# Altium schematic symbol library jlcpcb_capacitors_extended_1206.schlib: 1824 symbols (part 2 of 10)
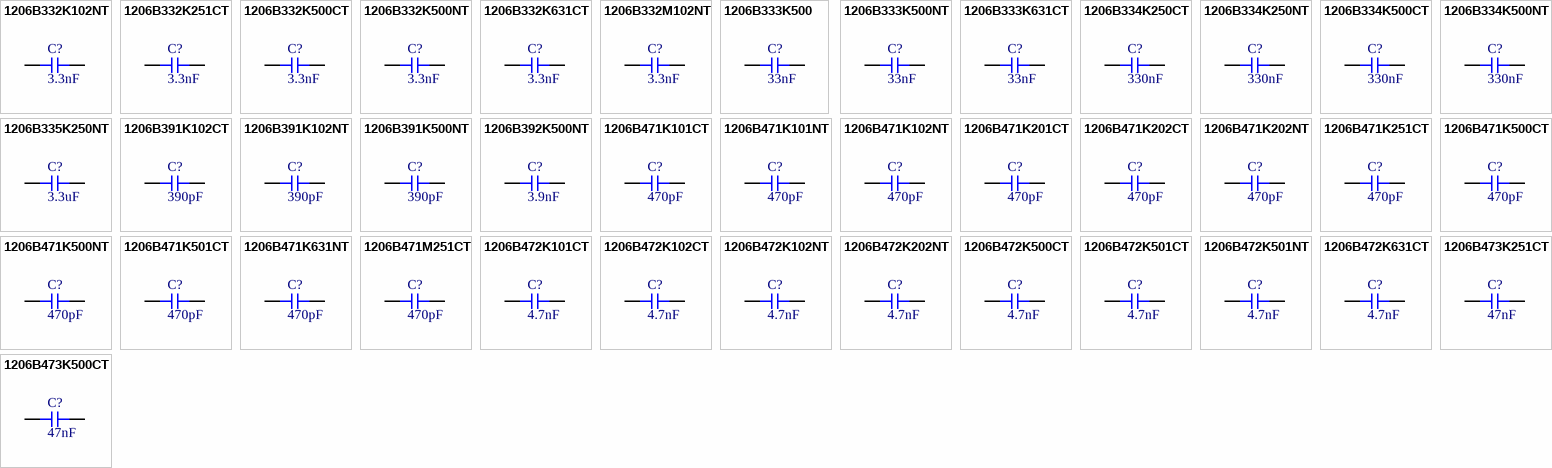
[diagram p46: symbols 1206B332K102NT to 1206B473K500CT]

## 1206B471K102NT
designator C?  Capacitance: 470pF  (hidden comment: *)
Capacitor, Ceramic (MLCC), 470pF, ±10%, 1kV, X7R, ±10%, SMD 1206; Manufacturer: FH(Guangdong Fenghua Advanced Tech); Manufacturer Part Number: 1206B471K102NT
footprint CAP-1206 (1206 (3216M) Capacitor)
pins: 1, 2

## 1206B471K201CT
designator C?  Capacitance: 470pF  (hidden comment: *)
Capacitor, Ceramic (MLCC), 470pF, ±10%, 200V, X7R, ±10%, SMD 1206; Manufacturer: Walsin Tech Corp; Manufacturer Part Number: 1206B471K201CT
footprint CAP-1206 (1206 (3216M) Capacitor)
pins: 1, 2

## 1206B471K202CT
designator C?  Capacitance: 470pF  (hidden comment: *)
Capacitor, Ceramic (MLCC), 470pF, ±10%, 2kV, X7R, ±10%, SMD 1206; Manufacturer: Walsin Tech Corp; Manufacturer Part Number: 1206B471K202CT
footprint CAP-1206 (1206 (3216M) Capacitor)
pins: 1, 2

## 1206B471K202NT
designator C?  Capacitance: 470pF  (hidden comment: *)
Capacitor, Ceramic (MLCC), 470pF, ±10%, 2kV, X7R, ±10%, SMD 1206; Manufacturer: FH(Guangdong Fenghua Advanced Tech); Manufacturer Part Number: 1206B471K202NT
footprint CAP-1206 (1206 (3216M) Capacitor)
pins: 1, 2

## 1206B471K251CT
designator C?  Capacitance: 470pF  (hidden comment: *)
Capacitor, Ceramic (MLCC), 470pF, ±10%, 250V, X7R, ±10%, SMD 1206; Manufacturer: Walsin Tech Corp; Manufacturer Part Number: 1206B471K251CT
footprint CAP-1206 (1206 (3216M) Capacitor)
pins: 1, 2

## 1206B471K500CT
designator C?  Capacitance: 470pF  (hidden comment: *)
Capacitor, Ceramic (MLCC), 470pF, ±10%, 50V, X7R, ±10%, SMD 1206; Manufacturer: Walsin Tech Corp; Manufacturer Part Number: 1206B471K500CT
footprint CAP-1206 (1206 (3216M) Capacitor)
pins: 1, 2

## 1206B471K500NT
designator C?  Capacitance: 470pF  (hidden comment: *)
Capacitor, Ceramic (MLCC), 470pF, ±10%, 50V, X7R, ±10%, SMD 1206; Manufacturer: FH(Guangdong Fenghua Advanced Tech); Manufacturer Part Number: 1206B471K500NT
footprint CAP-1206 (1206 (3216M) Capacitor)
pins: 1, 2

## 1206B471K501CT
designator C?  Capacitance: 470pF  (hidden comment: *)
Capacitor, Ceramic (MLCC), 470pF, ±10%, 500V, X7R, ±10%, SMD 1206; Manufacturer: Walsin Tech Corp; Manufacturer Part Number: 1206B471K501CT
footprint CAP-1206 (1206 (3216M) Capacitor)
pins: 1, 2

## 1206B471K631NT
designator C?  Capacitance: 470pF  (hidden comment: *)
Capacitor, Ceramic (MLCC), 470pF, ±10%, 630V, ±10%, SMD 1206; Manufacturer: FH(Guangdong Fenghua Advanced Tech); Manufacturer Part Number: 1206B471K631NT
footprint CAP-1206 (1206 (3216M) Capacitor)
pins: 1, 2

## 1206B471M251CT
designator C?  Capacitance: 470pF  (hidden comment: *)
Capacitor, Ceramic (MLCC), 470pF, ±20%, 250V, X7R, ±20%, SMD 1206; Manufacturer: Walsin Tech Corp; Manufacturer Part Number: 1206B471M251CT
footprint CAP-1206 (1206 (3216M) Capacitor)
pins: 1, 2

## 1206B472K101CT
designator C?  Capacitance: 4.7nF  (hidden comment: *)
Capacitor, Ceramic (MLCC), 4.7nF, ±10%, 100V, X7R, ±10%, SMD 1206; Manufacturer: Walsin Tech Corp; Manufacturer Part Number: 1206B472K101CT
footprint CAP-1206 (1206 (3216M) Capacitor)
pins: 1, 2

## 1206B472K102CT
designator C?  Capacitance: 4.7nF  (hidden comment: *)
Capacitor, Ceramic (MLCC), 4.7nF, ±10%, 1kV, X7R, ±10%, SMD 1206; Manufacturer: Walsin Tech Corp; Manufacturer Part Number: 1206B472K102CT
footprint CAP-1206 (1206 (3216M) Capacitor)
pins: 1, 2

## 1206B472K102NT
designator C?  Capacitance: 4.7nF  (hidden comment: *)
Capacitor, Ceramic (MLCC), 4.7nF, ±10%, 1kV, X7R, ±10%, SMD 1206; Manufacturer: FH(Guangdong Fenghua Advanced Tech); Manufacturer Part Number: 1206B472K102NT
footprint CAP-1206 (1206 (3216M) Capacitor)
pins: 1, 2

## 1206B472K202NT
designator C?  Capacitance: 4.7nF  (hidden comment: *)
Capacitor, Ceramic (MLCC), 4.7nF, ±10%, 2kV, X7R, ±10%, SMD 1206; Manufacturer: FH(Guangdong Fenghua Advanced Tech); Manufacturer Part Number: 1206B472K202NT
footprint CAP-1206 (1206 (3216M) Capacitor)
pins: 1, 2

## 1206B472K500CT
designator C?  Capacitance: 4.7nF  (hidden comment: *)
Capacitor, Ceramic (MLCC), 4.7nF, ±10%, 50V, X7R, ±10%, SMD 1206; Manufacturer: Walsin Tech Corp; Manufacturer Part Number: 1206B472K500CT
footprint CAP-1206 (1206 (3216M) Capacitor)
pins: 1, 2

## 1206B472K501CT
designator C?  Capacitance: 4.7nF  (hidden comment: *)
Capacitor, Ceramic (MLCC), 4.7nF, ±10%, 500V, X7R, ±10%, SMD 1206; Manufacturer: Walsin Tech Corp; Manufacturer Part Number: 1206B472K501CT
footprint CAP-1206 (1206 (3216M) Capacitor)
pins: 1, 2

## 1206B472K501NT
designator C?  Capacitance: 4.7nF  (hidden comment: *)
Capacitor, Ceramic (MLCC), 4.7nF, ±10%, 500V, X7R, ±10%, SMD 1206; Manufacturer: FH(Guangdong Fenghua Advanced Tech); Manufacturer Part Number: 1206B472K501NT
footprint CAP-1206 (1206 (3216M) Capacitor)
pins: 1, 2

## 1206B472K631CT
designator C?  Capacitance: 4.7nF  (hidden comment: *)
Capacitor, Ceramic (MLCC), 4.7nF, ±10%, 630V, X7R, ±10%, SMD 1206; Manufacturer: Walsin Tech Corp; Manufacturer Part Number: 1206B472K631CT
footprint CAP-1206 (1206 (3216M) Capacitor)
pins: 1, 2

## 1206B473K251CT
designator C?  Capacitance: 47nF  (hidden comment: *)
Capacitor, Ceramic (MLCC), 47nF, ±10%, 250V, X7R, ±10%, SMD 1206; Manufacturer: Walsin Tech Corp; Manufacturer Part Number: 1206B473K251CT
footprint CAP-1206 (1206 (3216M) Capacitor)
pins: 1, 2

## 1206B473K500CT
designator C?  Capacitance: 47nF  (hidden comment: *)
Capacitor, Ceramic (MLCC), 47nF, ±10%, 50V, X7R, ±10%, SMD 1206; Manufacturer: Walsin Tech Corp; Manufacturer Part Number: 1206B473K500CT
footprint CAP-1206 (1206 (3216M) Capacitor)
pins: 1, 2

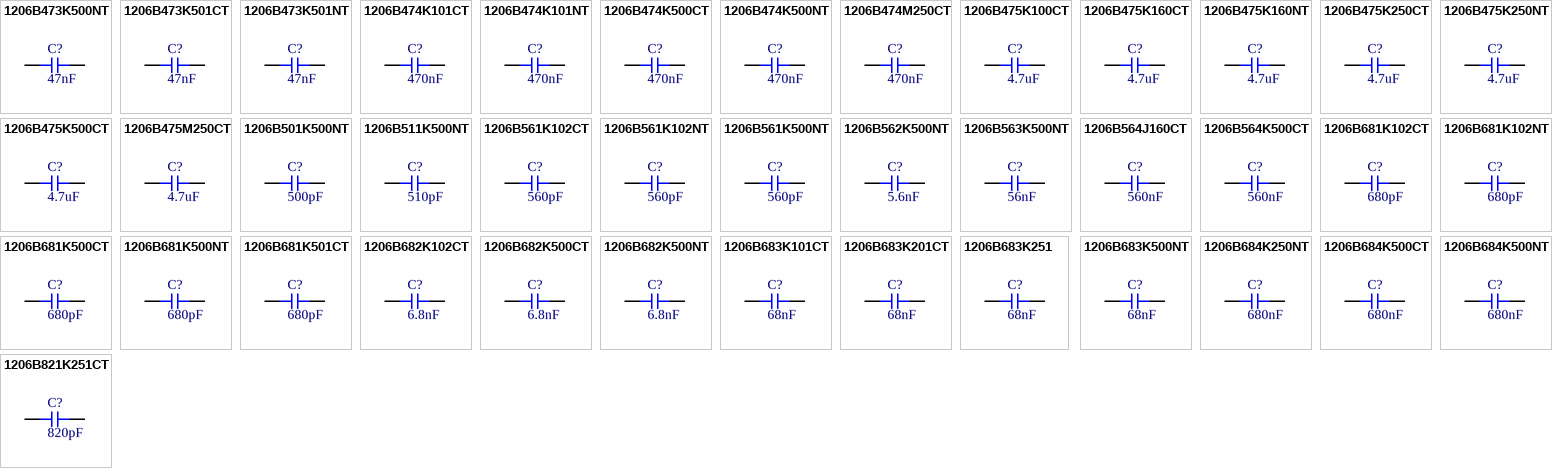
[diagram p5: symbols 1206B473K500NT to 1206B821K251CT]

## 1206B473K500NT
designator C?  Capacitance: 47nF  (hidden comment: *)
Capacitor, Ceramic (MLCC), 47nF, ±10%, 50V, X7R, ±10%, SMD 1206; Manufacturer: FH(Guangdong Fenghua Advanced Tech); Manufacturer Part Number: 1206B473K500NT
footprint CAP-1206 (1206 (3216M) Capacitor)
pins: 1, 2

## 1206B473K501CT
designator C?  Capacitance: 47nF  (hidden comment: *)
Capacitor, Ceramic (MLCC), 47nF, ±10%, 500V, X7R, ±10%, SMD 1206; Manufacturer: Walsin Tech Corp; Manufacturer Part Number: 1206B473K501CT
footprint CAP-1206 (1206 (3216M) Capacitor)
pins: 1, 2

## 1206B473K501NT
designator C?  Capacitance: 47nF  (hidden comment: *)
Capacitor, Ceramic (MLCC), 47nF, ±10%, 500V, X7R, ±10%, SMD 1206; Manufacturer: FH(Guangdong Fenghua Advanced Tech); Manufacturer Part Number: 1206B473K501NT
footprint CAP-1206 (1206 (3216M) Capacitor)
pins: 1, 2

## 1206B474K101CT
designator C?  Capacitance: 470nF  (hidden comment: *)
Capacitor, Ceramic (MLCC), 470nF, ±10%, 100V, X7R, ±10%, SMD 1206; Manufacturer: Walsin Tech Corp; Manufacturer Part Number: 1206B474K101CT
footprint CAP-1206 (1206 (3216M) Capacitor)
pins: 1, 2

## 1206B474K101NT
designator C?  Capacitance: 470nF  (hidden comment: *)
Capacitor, Ceramic (MLCC), 470nF, ±10%, 100V, X7R, ±10%, SMD 1206; Manufacturer: FH(Guangdong Fenghua Advanced Tech); Manufacturer Part Number: 1206B474K101NT
footprint CAP-1206 (1206 (3216M) Capacitor)
pins: 1, 2

## 1206B474K500CT
designator C?  Capacitance: 470nF  (hidden comment: *)
Capacitor, Ceramic (MLCC), 470nF, ±10%, 50V, X7R, ±10%, SMD 1206; Manufacturer: Walsin Tech Corp; Manufacturer Part Number: 1206B474K500CT
footprint CAP-1206 (1206 (3216M) Capacitor)
pins: 1, 2

## 1206B474K500NT
designator C?  Capacitance: 470nF  (hidden comment: *)
Capacitor, Ceramic (MLCC), 470nF, ±10%, 50V, X7R, ±10%, SMD 1206; Manufacturer: FH(Guangdong Fenghua Advanced Tech); Manufacturer Part Number: 1206B474K500NT
footprint CAP-1206 (1206 (3216M) Capacitor)
pins: 1, 2

## 1206B474M250CT
designator C?  Capacitance: 470nF  (hidden comment: *)
Capacitor, Ceramic (MLCC), 470nF, ±20%, 25V, X7R, ±20%, SMD 1206; Manufacturer: Walsin Tech Corp; Manufacturer Part Number: 1206B474M250CT
footprint CAP-1206 (1206 (3216M) Capacitor)
pins: 1, 2

## 1206B475K100CT
designator C?  Capacitance: 4.7uF  (hidden comment: *)
Capacitor, Ceramic (MLCC), 4.7uF, ±10%, 10V, X7R, ±10%, SMD 1206; Manufacturer: Walsin Tech Corp; Manufacturer Part Number: 1206B475K100CT
footprint CAP-1206 (1206 (3216M) Capacitor)
pins: 1, 2

## 1206B475K160CT
designator C?  Capacitance: 4.7uF  (hidden comment: *)
Capacitor, Ceramic (MLCC), 4.7uF, ±10%, 16V, X7R, ±10%, SMD 1206; Manufacturer: Walsin Tech Corp; Manufacturer Part Number: 1206B475K160CT
footprint CAP-1206 (1206 (3216M) Capacitor)
pins: 1, 2

## 1206B475K160NT
designator C?  Capacitance: 4.7uF  (hidden comment: *)
Capacitor, Ceramic (MLCC), 4.7uF, ±10%, 16V, X7R, ±10%, SMD 1206; Manufacturer: FH(Guangdong Fenghua Advanced Tech); Manufacturer Part Number: 1206B475K160NT
footprint CAP-1206 (1206 (3216M) Capacitor)
pins: 1, 2

## 1206B475K250CT
designator C?  Capacitance: 4.7uF  (hidden comment: *)
Capacitor, Ceramic (MLCC), 4.7uF, ±10%, 25V, X7R, ±10%, SMD 1206; Manufacturer: Walsin Tech Corp; Manufacturer Part Number: 1206B475K250CT
footprint CAP-1206 (1206 (3216M) Capacitor)
pins: 1, 2

## 1206B475K250NT
designator C?  Capacitance: 4.7uF  (hidden comment: *)
Capacitor, Ceramic (MLCC), 4.7uF, ±10%, 25V, X7R, ±10%, SMD 1206; Manufacturer: FH(Guangdong Fenghua Advanced Tech); Manufacturer Part Number: 1206B475K250NT
footprint CAP-1206 (1206 (3216M) Capacitor)
pins: 1, 2

## 1206B475K500CT
designator C?  Capacitance: 4.7uF  (hidden comment: *)
Capacitor, Ceramic (MLCC), 4.7uF, ±10%, 50V, X7R, ±10%, SMD 1206; Manufacturer: Walsin Tech Corp; Manufacturer Part Number: 1206B475K500CT
footprint CAP-1206 (1206 (3216M) Capacitor)
pins: 1, 2

## 1206B475M250CT
designator C?  Capacitance: 4.7uF  (hidden comment: *)
Capacitor, Ceramic (MLCC), 4.7uF, ±20%, 25V, X7R, ±20%, SMD 1206; Manufacturer: Walsin Tech Corp; Manufacturer Part Number: 1206B475M250CT
footprint CAP-1206 (1206 (3216M) Capacitor)
pins: 1, 2

## 1206B501K500NT
designator C?  Capacitance: 500pF  (hidden comment: *)
Capacitor, Ceramic (MLCC), 500pF, ±10%, 50V, X7R, ±10%, SMD 1206; Manufacturer: FH(Guangdong Fenghua Advanced Tech); Manufacturer Part Number: 1206B501K500NT
footprint CAP-1206 (1206 (3216M) Capacitor)
pins: 1, 2

## 1206B511K500NT
designator C?  Capacitance: 510pF  (hidden comment: *)
Capacitor, Ceramic (MLCC), 510pF, ±10%, 50V, X7R, ±10%, SMD 1206; Manufacturer: FH(Guangdong Fenghua Advanced Tech); Manufacturer Part Number: 1206B511K500NT
footprint CAP-1206 (1206 (3216M) Capacitor)
pins: 1, 2

## 1206B561K102CT
designator C?  Capacitance: 560pF  (hidden comment: *)
Capacitor, Ceramic (MLCC), 560pF, ±10%, 1kV, X7R, ±10%, SMD 1206; Manufacturer: Walsin Tech Corp; Manufacturer Part Number: 1206B561K102CT
footprint CAP-1206 (1206 (3216M) Capacitor)
pins: 1, 2

## 1206B561K102NT
designator C?  Capacitance: 560pF  (hidden comment: *)
Capacitor, Ceramic (MLCC), 560pF, ±10%, 1kV, X7R, ±10%, SMD 1206; Manufacturer: FH(Guangdong Fenghua Advanced Tech); Manufacturer Part Number: 1206B561K102NT
footprint CAP-1206 (1206 (3216M) Capacitor)
pins: 1, 2

## 1206B561K500NT
designator C?  Capacitance: 560pF  (hidden comment: *)
Capacitor, Ceramic (MLCC), 560pF, ±10%, 50V, X7R, ±10%, SMD 1206; Manufacturer: FH(Guangdong Fenghua Advanced Tech); Manufacturer Part Number: 1206B561K500NT
footprint CAP-1206 (1206 (3216M) Capacitor)
pins: 1, 2

## 1206B562K500NT
designator C?  Capacitance: 5.6nF  (hidden comment: *)
Capacitor, Ceramic (MLCC), 5.6nF, ±10%, 50V, X7R, ±10%, SMD 1206; Manufacturer: FH(Guangdong Fenghua Advanced Tech); Manufacturer Part Number: 1206B562K500NT
footprint CAP-1206 (1206 (3216M) Capacitor)
pins: 1, 2

## 1206B563K500NT
designator C?  Capacitance: 56nF  (hidden comment: *)
Capacitor, Ceramic (MLCC), 56nF, ±10%, 50V, X7R, ±10%, SMD 1206; Manufacturer: FH(Guangdong Fenghua Advanced Tech); Manufacturer Part Number: 1206B563K500NT
footprint CAP-1206 (1206 (3216M) Capacitor)
pins: 1, 2

## 1206B564J160CT
designator C?  Capacitance: 560nF  (hidden comment: *)
Capacitor, Ceramic (MLCC), 560nF, ±5%, 16V, X7R, ±5%, SMD 1206; Manufacturer: Walsin Tech Corp; Manufacturer Part Number: 1206B564J160CT
footprint CAP-1206 (1206 (3216M) Capacitor)
pins: 1, 2

## 1206B564K500CT
designator C?  Capacitance: 560nF  (hidden comment: *)
Capacitor, Ceramic (MLCC), 560nF, ±10%, 50V, X7R, ±10%, SMD 1206; Manufacturer: Walsin Tech Corp; Manufacturer Part Number: 1206B564K500CT
footprint CAP-1206 (1206 (3216M) Capacitor)
pins: 1, 2

## 1206B681K102CT
designator C?  Capacitance: 680pF  (hidden comment: *)
Capacitor, Ceramic (MLCC), 680pF, ±10%, 1kV, X7R, ±10%, SMD 1206; Manufacturer: Walsin Tech Corp; Manufacturer Part Number: 1206B681K102CT
footprint CAP-1206 (1206 (3216M) Capacitor)
pins: 1, 2

## 1206B681K102NT
designator C?  Capacitance: 680pF  (hidden comment: *)
Capacitor, Ceramic (MLCC), 680pF, ±10%, 1kV, X7R, ±10%, SMD 1206; Manufacturer: FH(Guangdong Fenghua Advanced Tech); Manufacturer Part Number: 1206B681K102NT
footprint CAP-1206 (1206 (3216M) Capacitor)
pins: 1, 2

## 1206B681K500CT
designator C?  Capacitance: 680pF  (hidden comment: *)
Capacitor, Ceramic (MLCC), 680pF, ±10%, 50V, X7R, ±10%, SMD 1206; Manufacturer: Walsin Tech Corp; Manufacturer Part Number: 1206B681K500CT
footprint CAP-1206 (1206 (3216M) Capacitor)
pins: 1, 2

## 1206B681K500NT
designator C?  Capacitance: 680pF  (hidden comment: *)
Capacitor, Ceramic (MLCC), 680pF, ±10%, 50V, X7R, ±10%, SMD 1206; Manufacturer: FH(Guangdong Fenghua Advanced Tech); Manufacturer Part Number: 1206B681K500NT
footprint CAP-1206 (1206 (3216M) Capacitor)
pins: 1, 2

## 1206B681K501CT
designator C?  Capacitance: 680pF  (hidden comment: *)
Capacitor, Ceramic (MLCC), 680pF, ±10%, 500V, X7R, ±10%, SMD 1206; Manufacturer: Walsin Tech Corp; Manufacturer Part Number: 1206B681K501CT
footprint CAP-1206 (1206 (3216M) Capacitor)
pins: 1, 2

## 1206B682K102CT
designator C?  Capacitance: 6.8nF  (hidden comment: *)
Capacitor, Ceramic (MLCC), 6.8nF, ±10%, 1kV, X7R, ±10%, SMD 1206; Manufacturer: Walsin Tech Corp; Manufacturer Part Number: 1206B682K102CT
footprint CAP-1206 (1206 (3216M) Capacitor)
pins: 1, 2

## 1206B682K500CT
designator C?  Capacitance: 6.8nF  (hidden comment: *)
Capacitor, Ceramic (MLCC), 6.8nF, ±10%, 50V, X7R, ±10%, SMD 1206; Manufacturer: Walsin Tech Corp; Manufacturer Part Number: 1206B682K500CT
footprint CAP-1206 (1206 (3216M) Capacitor)
pins: 1, 2

## 1206B682K500NT
designator C?  Capacitance: 6.8nF  (hidden comment: *)
Capacitor, Ceramic (MLCC), 6.8nF, ±10%, 50V, X7R, ±10%, SMD 1206; Manufacturer: FH(Guangdong Fenghua Advanced Tech); Manufacturer Part Number: 1206B682K500NT
footprint CAP-1206 (1206 (3216M) Capacitor)
pins: 1, 2

## 1206B683K101CT
designator C?  Capacitance: 68nF  (hidden comment: *)
Capacitor, Ceramic (MLCC), 68nF, ±10%, 100V, X7R, ±10%, SMD 1206; Manufacturer: Walsin Tech Corp; Manufacturer Part Number: 1206B683K101CT
footprint CAP-1206 (1206 (3216M) Capacitor)
pins: 1, 2

## 1206B683K201CT
designator C?  Capacitance: 68nF  (hidden comment: *)
Capacitor, Ceramic (MLCC), 68nF, ±10%, 200V, X7R, ±10%, SMD 1206; Manufacturer: Walsin Tech Corp; Manufacturer Part Number: 1206B683K201CT
footprint CAP-1206 (1206 (3216M) Capacitor)
pins: 1, 2

## 1206B683K251
designator C?  Capacitance: 68nF  (hidden comment: *)
Capacitor, Ceramic (MLCC), 68nF, ±10%, 250V, X7R, ±10%, SMD 1206; Manufacturer: Walsin Tech Corp; Manufacturer Part Number: 1206B683K251
footprint CAP-1206 (1206 (3216M) Capacitor)
pins: 1, 2

## 1206B683K500NT
designator C?  Capacitance: 68nF  (hidden comment: *)
Capacitor, Ceramic (MLCC), 68nF, ±10%, 50V, X7R, ±10%, SMD 1206; Manufacturer: FH(Guangdong Fenghua Advanced Tech); Manufacturer Part Number: 1206B683K500NT
footprint CAP-1206 (1206 (3216M) Capacitor)
pins: 1, 2

## 1206B684K250NT
designator C?  Capacitance: 680nF  (hidden comment: *)
Capacitor, Ceramic (MLCC), 680nF, ±10%, 25V, X7R, ±10%, SMD 1206; Manufacturer: FH(Guangdong Fenghua Advanced Tech); Manufacturer Part Number: 1206B684K250NT
footprint CAP-1206 (1206 (3216M) Capacitor)
pins: 1, 2

## 1206B684K500CT
designator C?  Capacitance: 680nF  (hidden comment: *)
Capacitor, Ceramic (MLCC), 680nF, ±10%, 50V, X7R, ±10%, SMD 1206; Manufacturer: Walsin Tech Corp; Manufacturer Part Number: 1206B684K500CT
footprint CAP-1206 (1206 (3216M) Capacitor)
pins: 1, 2

## 1206B684K500NT
designator C?  Capacitance: 680nF  (hidden comment: *)
Capacitor, Ceramic (MLCC), 680nF, ±10%, 50V, X7R, ±10%, SMD 1206; Manufacturer: FH(Guangdong Fenghua Advanced Tech); Manufacturer Part Number: 1206B684K500NT
footprint CAP-1206 (1206 (3216M) Capacitor)
pins: 1, 2

## 1206B821K251CT
designator C?  Capacitance: 820pF  (hidden comment: *)
Capacitor, Ceramic (MLCC), 820pF, ±10%, 250V, X7R, ±10%, SMD 1206; Manufacturer: Walsin Tech Corp; Manufacturer Part Number: 1206B821K251CT
footprint CAP-1206 (1206 (3216M) Capacitor)
pins: 1, 2

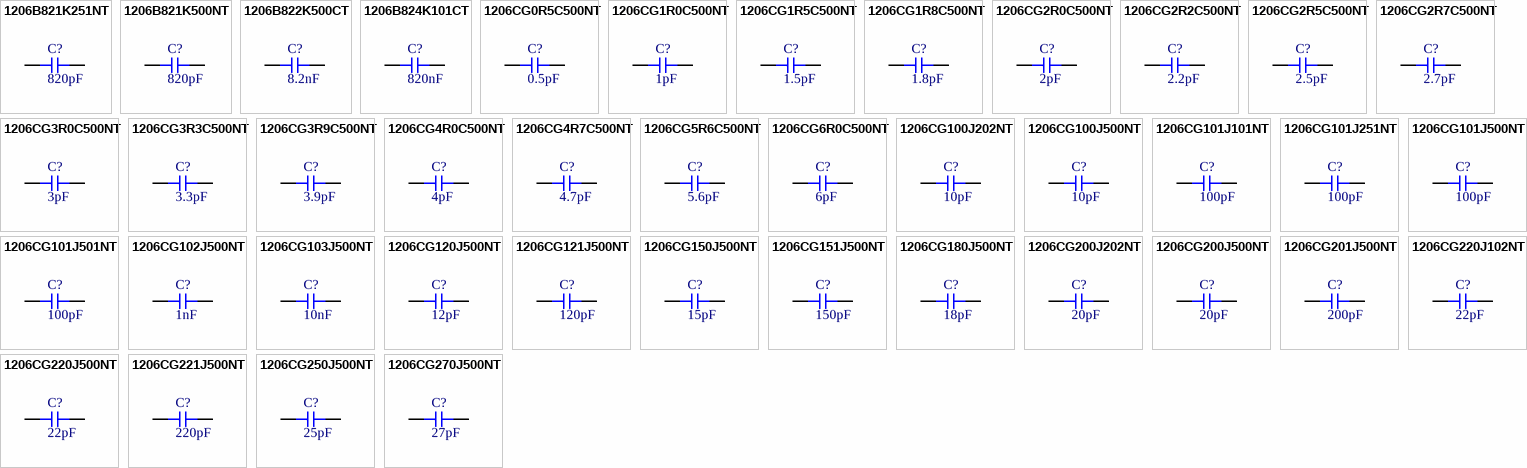
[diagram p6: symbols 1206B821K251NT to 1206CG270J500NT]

## 1206B821K251NT
designator C?  Capacitance: 820pF  (hidden comment: *)
Capacitor, Ceramic (MLCC), 820pF, ±10%, 250V, X7R, ±10%, SMD 1206; Manufacturer: FH(Guangdong Fenghua Advanced Tech); Manufacturer Part Number: 1206B821K251NT
footprint CAP-1206 (1206 (3216M) Capacitor)
pins: 1, 2

## 1206B821K500NT
designator C?  Capacitance: 820pF  (hidden comment: *)
Capacitor, Ceramic (MLCC), 820pF, ±10%, 50V, X7R, ±10%, SMD 1206; Manufacturer: FH(Guangdong Fenghua Advanced Tech); Manufacturer Part Number: 1206B821K500NT
footprint CAP-1206 (1206 (3216M) Capacitor)
pins: 1, 2

## 1206B822K500CT
designator C?  Capacitance: 8.2nF  (hidden comment: *)
Capacitor, Ceramic (MLCC), 8.2nF, ±10%, 50V, X7R, ±10%, SMD 1206; Manufacturer: Walsin Tech Corp; Manufacturer Part Number: 1206B822K500CT
footprint CAP-1206 (1206 (3216M) Capacitor)
pins: 1, 2

## 1206B824K101CT
designator C?  Capacitance: 820nF  (hidden comment: *)
Capacitor, Ceramic (MLCC), 820nF, ±10%, 100V, X7R, ±10%, SMD 1206; Manufacturer: Walsin Tech Corp; Manufacturer Part Number: 1206B824K101CT
footprint CAP-1206 (1206 (3216M) Capacitor)
pins: 1, 2

## 1206CG0R5C500NT
designator C?  Capacitance: 0.5pF  (hidden comment: *)
Capacitor, Ceramic (MLCC), 0.5pF, ±0.25pF, 50V, C0G, ±0.25pF, SMD 1206; Manufacturer: FH(Guangdong Fenghua Advanced Tech); Manufacturer Part Number: 1206CG0R5C500NT
footprint CAP-1206 (1206 (3216M) Capacitor)
pins: 1, 2

## 1206CG1R0C500NT
designator C?  Capacitance: 1pF  (hidden comment: *)
Capacitor, Ceramic (MLCC), 1pF, ±0.25pF, 50V, C0G, ±0.25pF, SMD 1206; Manufacturer: FH(Guangdong Fenghua Advanced Tech); Manufacturer Part Number: 1206CG1R0C500NT
footprint CAP-1206 (1206 (3216M) Capacitor)
pins: 1, 2

## 1206CG1R5C500NT
designator C?  Capacitance: 1.5pF  (hidden comment: *)
Capacitor, Ceramic (MLCC), 1.5pF, ±0.25pF, 50V, C0G, ±0.25pF, SMD 1206; Manufacturer: FH(Guangdong Fenghua Advanced Tech); Manufacturer Part Number: 1206CG1R5C500NT
footprint CAP-1206 (1206 (3216M) Capacitor)
pins: 1, 2

## 1206CG1R8C500NT
designator C?  Capacitance: 1.8pF  (hidden comment: *)
Capacitor, Ceramic (MLCC), 1.8pF, ±0.25pF, 50V, C0G, ±0.25pF, SMD 1206; Manufacturer: FH(Guangdong Fenghua Advanced Tech); Manufacturer Part Number: 1206CG1R8C500NT
footprint CAP-1206 (1206 (3216M) Capacitor)
pins: 1, 2

## 1206CG2R0C500NT
designator C?  Capacitance: 2pF  (hidden comment: *)
Capacitor, Ceramic (MLCC), 2pF, ±0.25pF, 50V, C0G, ±0.25pF, SMD 1206; Manufacturer: FH(Guangdong Fenghua Advanced Tech); Manufacturer Part Number: 1206CG2R0C500NT
footprint CAP-1206 (1206 (3216M) Capacitor)
pins: 1, 2

## 1206CG2R2C500NT
designator C?  Capacitance: 2.2pF  (hidden comment: *)
Capacitor, Ceramic (MLCC), 2.2pF, ±0.25pF, 50V, C0G, ±0.25pF, SMD 1206; Manufacturer: FH(Guangdong Fenghua Advanced Tech); Manufacturer Part Number: 1206CG2R2C500NT
footprint CAP-1206 (1206 (3216M) Capacitor)
pins: 1, 2

## 1206CG2R5C500NT
designator C?  Capacitance: 2.5pF  (hidden comment: *)
Capacitor, Ceramic (MLCC), 2.5pF, ±0.25pF, 50V, C0G, ±0.25pF, SMD 1206; Manufacturer: FH(Guangdong Fenghua Advanced Tech); Manufacturer Part Number: 1206CG2R5C500NT
footprint CAP-1206 (1206 (3216M) Capacitor)
pins: 1, 2

## 1206CG2R7C500NT
designator C?  Capacitance: 2.7pF  (hidden comment: *)
Capacitor, Ceramic (MLCC), 2.7pF, ±0.25pF, 50V, C0G, ±0.25pF, SMD 1206; Manufacturer: FH(Guangdong Fenghua Advanced Tech); Manufacturer Part Number: 1206CG2R7C500NT
footprint CAP-1206 (1206 (3216M) Capacitor)
pins: 1, 2

## 1206CG3R0C500NT
designator C?  Capacitance: 3pF  (hidden comment: *)
Capacitor, Ceramic (MLCC), 3pF, ±0.25pF, 50V, C0G, ±0.25pF, SMD 1206; Manufacturer: FH(Guangdong Fenghua Advanced Tech); Manufacturer Part Number: 1206CG3R0C500NT
footprint CAP-1206 (1206 (3216M) Capacitor)
pins: 1, 2

## 1206CG3R3C500NT
designator C?  Capacitance: 3.3pF  (hidden comment: *)
Capacitor, Ceramic (MLCC), 3.3pF, ±0.25pF, 50V, C0G, ±0.25pF, SMD 1206; Manufacturer: FH(Guangdong Fenghua Advanced Tech); Manufacturer Part Number: 1206CG3R3C500NT
footprint CAP-1206 (1206 (3216M) Capacitor)
pins: 1, 2

## 1206CG3R9C500NT
designator C?  Capacitance: 3.9pF  (hidden comment: *)
Capacitor, Ceramic (MLCC), 3.9pF, ±0.25pF, 50V, C0G, ±0.25pF, SMD 1206; Manufacturer: FH(Guangdong Fenghua Advanced Tech); Manufacturer Part Number: 1206CG3R9C500NT
footprint CAP-1206 (1206 (3216M) Capacitor)
pins: 1, 2

## 1206CG4R0C500NT
designator C?  Capacitance: 4pF  (hidden comment: *)
Capacitor, Ceramic (MLCC), 4pF, ±0.25pF, 50V, C0G, ±0.25pF, SMD 1206; Manufacturer: FH(Guangdong Fenghua Advanced Tech); Manufacturer Part Number: 1206CG4R0C500NT
footprint CAP-1206 (1206 (3216M) Capacitor)
pins: 1, 2

## 1206CG4R7C500NT
designator C?  Capacitance: 4.7pF  (hidden comment: *)
Capacitor, Ceramic (MLCC), 4.7pF, ±0.25pF, 50V, C0G, ±0.25pF, SMD 1206; Manufacturer: FH(Guangdong Fenghua Advanced Tech); Manufacturer Part Number: 1206CG4R7C500NT
footprint CAP-1206 (1206 (3216M) Capacitor)
pins: 1, 2

## 1206CG5R6C500NT
designator C?  Capacitance: 5.6pF  (hidden comment: *)
Capacitor, Ceramic (MLCC), 5.6pF, ±0.25pF, 50V, ±0.25pF, SMD 1206; Manufacturer: FH(Guangdong Fenghua Advanced Tech); Manufacturer Part Number: 1206CG5R6C500NT
footprint CAP-1206 (1206 (3216M) Capacitor)
pins: 1, 2

## 1206CG6R0C500NT
designator C?  Capacitance: 6pF  (hidden comment: *)
Capacitor, Ceramic (MLCC), 6pF, ±0.25pF, 50V, C0G, ±0.25pF, SMD 1206; Manufacturer: FH(Guangdong Fenghua Advanced Tech); Manufacturer Part Number: 1206CG6R0C500NT
footprint CAP-1206 (1206 (3216M) Capacitor)
pins: 1, 2

## 1206CG100J202NT
designator C?  Capacitance: 10pF  (hidden comment: *)
Capacitor, Ceramic (MLCC), 10pF, ±5%, 2kV, ±5%, SMD 1206; Manufacturer: FH(Guangdong Fenghua Advanced Tech); Manufacturer Part Number: 1206CG100J202NT
footprint CAP-1206 (1206 (3216M) Capacitor)
pins: 1, 2

## 1206CG100J500NT
designator C?  Capacitance: 10pF  (hidden comment: *)
Capacitor, Ceramic (MLCC), 10pF, ±5%, 50V, C0G, ±5%, SMD 1206; Manufacturer: FH(Guangdong Fenghua Advanced Tech); Manufacturer Part Number: 1206CG100J500NT
footprint CAP-1206 (1206 (3216M) Capacitor)
pins: 1, 2

## 1206CG101J101NT
designator C?  Capacitance: 100pF  (hidden comment: *)
Capacitor, Ceramic (MLCC), 100pF, ±5%, 100V, C0G, ±5%, SMD 1206; Manufacturer: FH(Guangdong Fenghua Advanced Tech); Manufacturer Part Number: 1206CG101J101NT
footprint CAP-1206 (1206 (3216M) Capacitor)
pins: 1, 2

## 1206CG101J251NT
designator C?  Capacitance: 100pF  (hidden comment: *)
Capacitor, Ceramic (MLCC), 100pF, ±5%, 250V, C0G, ±5%, SMD 1206; Manufacturer: FH(Guangdong Fenghua Advanced Tech); Manufacturer Part Number: 1206CG101J251NT
footprint CAP-1206 (1206 (3216M) Capacitor)
pins: 1, 2

## 1206CG101J500NT
designator C?  Capacitance: 100pF  (hidden comment: *)
Capacitor, Ceramic (MLCC), 100pF, ±5%, 50V, C0G, ±5%, SMD 1206; Manufacturer: FH(Guangdong Fenghua Advanced Tech); Manufacturer Part Number: 1206CG101J500NT
footprint CAP-1206 (1206 (3216M) Capacitor)
pins: 1, 2

## 1206CG101J501NT
designator C?  Capacitance: 100pF  (hidden comment: *)
Capacitor, Ceramic (MLCC), 100pF, ±5%, 500V, C0G, ±5%, SMD 1206; Manufacturer: FH(Guangdong Fenghua Advanced Tech); Manufacturer Part Number: 1206CG101J501NT
footprint CAP-1206 (1206 (3216M) Capacitor)
pins: 1, 2

## 1206CG102J500NT
designator C?  Capacitance: 1nF  (hidden comment: *)
Capacitor, Ceramic (MLCC), 1nF, ±5%, 50V, C0G, ±5%, SMD 1206; Manufacturer: FH(Guangdong Fenghua Advanced Tech); Manufacturer Part Number: 1206CG102J500NT
footprint CAP-1206 (1206 (3216M) Capacitor)
pins: 1, 2

## 1206CG103J500NT
designator C?  Capacitance: 10nF  (hidden comment: *)
Capacitor, Ceramic (MLCC), 10nF, ±5%, 50V, C0G, ±5%, SMD 1206; Manufacturer: FH(Guangdong Fenghua Advanced Tech); Manufacturer Part Number: 1206CG103J500NT
footprint CAP-1206 (1206 (3216M) Capacitor)
pins: 1, 2

## 1206CG120J500NT
designator C?  Capacitance: 12pF  (hidden comment: *)
Capacitor, Ceramic (MLCC), 12pF, ±5%, 50V, C0G, ±5%, SMD 1206; Manufacturer: FH(Guangdong Fenghua Advanced Tech); Manufacturer Part Number: 1206CG120J500NT
footprint CAP-1206 (1206 (3216M) Capacitor)
pins: 1, 2

## 1206CG121J500NT
designator C?  Capacitance: 120pF  (hidden comment: *)
Capacitor, Ceramic (MLCC), 120pF, ±5%, 50V, C0G, ±5%, SMD 1206; Manufacturer: FH(Guangdong Fenghua Advanced Tech); Manufacturer Part Number: 1206CG121J500NT
footprint CAP-1206 (1206 (3216M) Capacitor)
pins: 1, 2

## 1206CG150J500NT
designator C?  Capacitance: 15pF  (hidden comment: *)
Capacitor, Ceramic (MLCC), 15pF, ±5%, 50V, C0G, ±5%, SMD 1206; Manufacturer: FH(Guangdong Fenghua Advanced Tech); Manufacturer Part Number: 1206CG150J500NT
footprint CAP-1206 (1206 (3216M) Capacitor)
pins: 1, 2

## 1206CG151J500NT
designator C?  Capacitance: 150pF  (hidden comment: *)
Capacitor, Ceramic (MLCC), 150pF, ±5%, 50V, C0G, ±5%, SMD 1206; Manufacturer: FH(Guangdong Fenghua Advanced Tech); Manufacturer Part Number: 1206CG151J500NT
footprint CAP-1206 (1206 (3216M) Capacitor)
pins: 1, 2

## 1206CG180J500NT
designator C?  Capacitance: 18pF  (hidden comment: *)
Capacitor, Ceramic (MLCC), 18pF, ±5%, 50V, C0G, ±5%, SMD 1206; Manufacturer: FH(Guangdong Fenghua Advanced Tech); Manufacturer Part Number: 1206CG180J500NT
footprint CAP-1206 (1206 (3216M) Capacitor)
pins: 1, 2

## 1206CG200J202NT
designator C?  Capacitance: 20pF  (hidden comment: *)
Capacitor, Ceramic (MLCC), 20pF, ±5%, 2kV, C0G, ±5%, SMD 1206; Manufacturer: FH(Guangdong Fenghua Advanced Tech); Manufacturer Part Number: 1206CG200J202NT
footprint CAP-1206 (1206 (3216M) Capacitor)
pins: 1, 2

## 1206CG200J500NT
designator C?  Capacitance: 20pF  (hidden comment: *)
Capacitor, Ceramic (MLCC), 20pF, ±5%, 50V, C0G, ±5%, SMD 1206; Manufacturer: FH(Guangdong Fenghua Advanced Tech); Manufacturer Part Number: 1206CG200J500NT
footprint CAP-1206 (1206 (3216M) Capacitor)
pins: 1, 2

## 1206CG201J500NT
designator C?  Capacitance: 200pF  (hidden comment: *)
Capacitor, Ceramic (MLCC), 200pF, ±5%, 50V, C0G, ±5%, SMD 1206; Manufacturer: FH(Guangdong Fenghua Advanced Tech); Manufacturer Part Number: 1206CG201J500NT
footprint CAP-1206 (1206 (3216M) Capacitor)
pins: 1, 2

## 1206CG220J102NT
designator C?  Capacitance: 22pF  (hidden comment: *)
Capacitor, Ceramic (MLCC), 22pF, ±5%, 1kV, C0G, ±5%, SMD 1206; Manufacturer: FH(Guangdong Fenghua Advanced Tech); Manufacturer Part Number: 1206CG220J102NT
footprint CAP-1206 (1206 (3216M) Capacitor)
pins: 1, 2

## 1206CG220J500NT
designator C?  Capacitance: 22pF  (hidden comment: *)
Capacitor, Ceramic (MLCC), 22pF, ±5%, 50V, C0G, ±5%, SMD 1206; Manufacturer: FH(Guangdong Fenghua Advanced Tech); Manufacturer Part Number: 1206CG220J500NT
footprint CAP-1206 (1206 (3216M) Capacitor)
pins: 1, 2

## 1206CG221J500NT
designator C?  Capacitance: 220pF  (hidden comment: *)
Capacitor, Ceramic (MLCC), 220pF, ±5%, 50V, C0G, ±5%, SMD 1206; Manufacturer: FH(Guangdong Fenghua Advanced Tech); Manufacturer Part Number: 1206CG221J500NT
footprint CAP-1206 (1206 (3216M) Capacitor)
pins: 1, 2

## 1206CG250J500NT
designator C?  Capacitance: 25pF  (hidden comment: *)
Capacitor, Ceramic (MLCC), 25pF, ±5%, 50V, C0G, ±5%, SMD 1206; Manufacturer: FH(Guangdong Fenghua Advanced Tech); Manufacturer Part Number: 1206CG250J500NT
footprint CAP-1206 (1206 (3216M) Capacitor)
pins: 1, 2

## 1206CG270J500NT
designator C?  Capacitance: 27pF  (hidden comment: *)
Capacitor, Ceramic (MLCC), 27pF, ±5%, 50V, C0G, ±5%, SMD 1206; Manufacturer: FH(Guangdong Fenghua Advanced Tech); Manufacturer Part Number: 1206CG270J500NT
footprint CAP-1206 (1206 (3216M) Capacitor)
pins: 1, 2

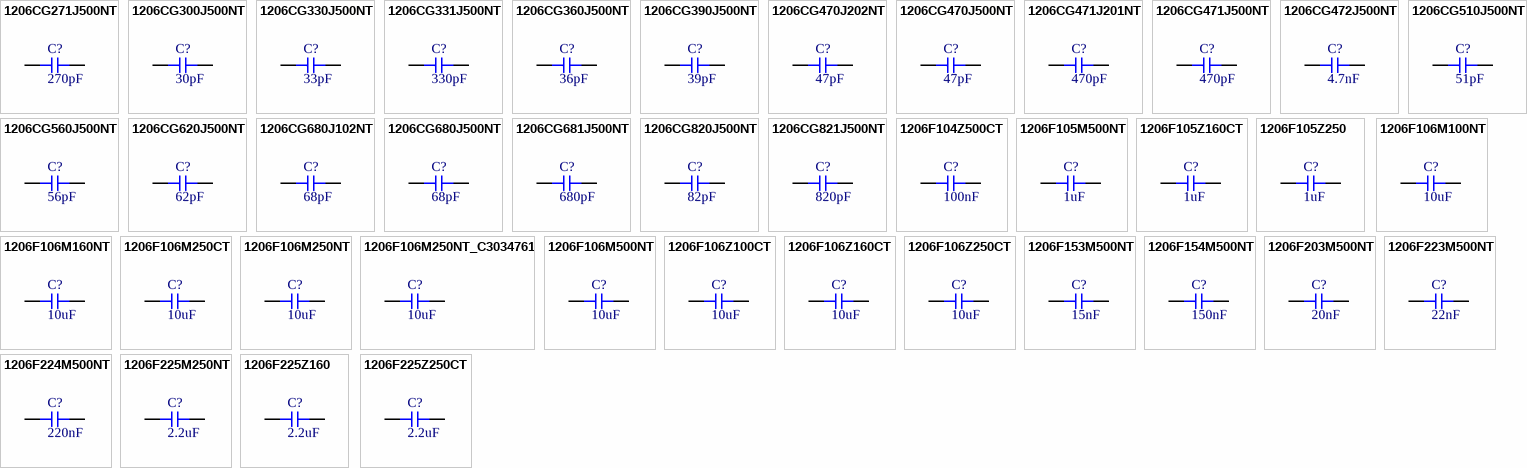
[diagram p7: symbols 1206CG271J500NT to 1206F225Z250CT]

## 1206CG271J500NT
designator C?  Capacitance: 270pF  (hidden comment: *)
Capacitor, Ceramic (MLCC), 270pF, ±5%, 50V, C0G, ±5%, SMD 1206; Manufacturer: FH(Guangdong Fenghua Advanced Tech); Manufacturer Part Number: 1206CG271J500NT
footprint CAP-1206 (1206 (3216M) Capacitor)
pins: 1, 2

## 1206CG300J500NT
designator C?  Capacitance: 30pF  (hidden comment: *)
Capacitor, Ceramic (MLCC), 30pF, ±5%, 50V, C0G, ±5%, SMD 1206; Manufacturer: FH(Guangdong Fenghua Advanced Tech); Manufacturer Part Number: 1206CG300J500NT
footprint CAP-1206 (1206 (3216M) Capacitor)
pins: 1, 2

## 1206CG330J500NT
designator C?  Capacitance: 33pF  (hidden comment: *)
Capacitor, Ceramic (MLCC), 33pF, ±5%, 50V, C0G, ±5%, SMD 1206; Manufacturer: FH(Guangdong Fenghua Advanced Tech); Manufacturer Part Number: 1206CG330J500NT
footprint CAP-1206 (1206 (3216M) Capacitor)
pins: 1, 2

## 1206CG331J500NT
designator C?  Capacitance: 330pF  (hidden comment: *)
Capacitor, Ceramic (MLCC), 330pF, ±5%, 50V, C0G, ±5%, SMD 1206; Manufacturer: FH(Guangdong Fenghua Advanced Tech); Manufacturer Part Number: 1206CG331J500NT
footprint CAP-1206 (1206 (3216M) Capacitor)
pins: 1, 2

## 1206CG360J500NT
designator C?  Capacitance: 36pF  (hidden comment: *)
Capacitor, Ceramic (MLCC), 36pF, ±5%, 50V, C0G, ±5%, SMD 1206; Manufacturer: FH(Guangdong Fenghua Advanced Tech); Manufacturer Part Number: 1206CG360J500NT
footprint CAP-1206 (1206 (3216M) Capacitor)
pins: 1, 2

## 1206CG390J500NT
designator C?  Capacitance: 39pF  (hidden comment: *)
Capacitor, Ceramic (MLCC), 39pF, ±5%, 50V, C0G, ±5%, SMD 1206; Manufacturer: FH(Guangdong Fenghua Advanced Tech); Manufacturer Part Number: 1206CG390J500NT
footprint CAP-1206 (1206 (3216M) Capacitor)
pins: 1, 2

## 1206CG470J202NT
designator C?  Capacitance: 47pF  (hidden comment: *)
Capacitor, Ceramic (MLCC), 47pF, ±5%, 2kV, C0G, ±5%, SMD 1206; Manufacturer: FH(Guangdong Fenghua Advanced Tech); Manufacturer Part Number: 1206CG470J202NT
footprint CAP-1206 (1206 (3216M) Capacitor)
pins: 1, 2

## 1206CG470J500NT
designator C?  Capacitance: 47pF  (hidden comment: *)
Capacitor, Ceramic (MLCC), 47pF, ±5%, 50V, C0G, ±5%, SMD 1206; Manufacturer: FH(Guangdong Fenghua Advanced Tech); Manufacturer Part Number: 1206CG470J500NT
footprint CAP-1206 (1206 (3216M) Capacitor)
pins: 1, 2

## 1206CG471J201NT
designator C?  Capacitance: 470pF  (hidden comment: *)
Capacitor, Ceramic (MLCC), 470pF, ±5%, 200V, ±5%, SMD 1206; Manufacturer: FH(Guangdong Fenghua Advanced Tech); Manufacturer Part Number: 1206CG471J201NT
footprint CAP-1206 (1206 (3216M) Capacitor)
pins: 1, 2

## 1206CG471J500NT
designator C?  Capacitance: 470pF  (hidden comment: *)
Capacitor, Ceramic (MLCC), 470pF, ±5%, 50V, C0G, ±5%, SMD 1206; Manufacturer: FH(Guangdong Fenghua Advanced Tech); Manufacturer Part Number: 1206CG471J500NT
footprint CAP-1206 (1206 (3216M) Capacitor)
pins: 1, 2

## 1206CG472J500NT
designator C?  Capacitance: 4.7nF  (hidden comment: *)
Capacitor, Ceramic (MLCC), 4.7nF, ±5%, 50V, C0G, ±5%, SMD 1206; Manufacturer: FH(Guangdong Fenghua Advanced Tech); Manufacturer Part Number: 1206CG472J500NT
footprint CAP-1206 (1206 (3216M) Capacitor)
pins: 1, 2

## 1206CG510J500NT
designator C?  Capacitance: 51pF  (hidden comment: *)
Capacitor, Ceramic (MLCC), 51pF, ±5%, 50V, C0G, ±5%, SMD 1206; Manufacturer: FH(Guangdong Fenghua Advanced Tech); Manufacturer Part Number: 1206CG510J500NT
footprint CAP-1206 (1206 (3216M) Capacitor)
pins: 1, 2

## 1206CG560J500NT
designator C?  Capacitance: 56pF  (hidden comment: *)
Capacitor, Ceramic (MLCC), 56pF, ±5%, 50V, C0G, ±5%, SMD 1206; Manufacturer: FH(Guangdong Fenghua Advanced Tech); Manufacturer Part Number: 1206CG560J500NT
footprint CAP-1206 (1206 (3216M) Capacitor)
pins: 1, 2

## 1206CG620J500NT
designator C?  Capacitance: 62pF  (hidden comment: *)
Capacitor, Ceramic (MLCC), 62pF, ±5%, 50V, C0G, ±5%, SMD 1206; Manufacturer: FH(Guangdong Fenghua Advanced Tech); Manufacturer Part Number: 1206CG620J500NT
footprint CAP-1206 (1206 (3216M) Capacitor)
pins: 1, 2

## 1206CG680J102NT
designator C?  Capacitance: 68pF  (hidden comment: *)
Capacitor, Ceramic (MLCC), 68pF, ±5%, 1kV, ±5%, SMD 1206; Manufacturer: FH(Guangdong Fenghua Advanced Tech); Manufacturer Part Number: 1206CG680J102NT
footprint CAP-1206 (1206 (3216M) Capacitor)
pins: 1, 2

## 1206CG680J500NT
designator C?  Capacitance: 68pF  (hidden comment: *)
Capacitor, Ceramic (MLCC), 68pF, ±5%, 50V, C0G, ±5%, SMD 1206; Manufacturer: FH(Guangdong Fenghua Advanced Tech); Manufacturer Part Number: 1206CG680J500NT
footprint CAP-1206 (1206 (3216M) Capacitor)
pins: 1, 2

## 1206CG681J500NT
designator C?  Capacitance: 680pF  (hidden comment: *)
Capacitor, Ceramic (MLCC), 680pF, ±5%, 50V, C0G, ±5%, SMD 1206; Manufacturer: FH(Guangdong Fenghua Advanced Tech); Manufacturer Part Number: 1206CG681J500NT
footprint CAP-1206 (1206 (3216M) Capacitor)
pins: 1, 2

## 1206CG820J500NT
designator C?  Capacitance: 82pF  (hidden comment: *)
Capacitor, Ceramic (MLCC), 82pF, ±5%, 50V, C0G, ±5%, SMD 1206; Manufacturer: FH(Guangdong Fenghua Advanced Tech); Manufacturer Part Number: 1206CG820J500NT
footprint CAP-1206 (1206 (3216M) Capacitor)
pins: 1, 2

## 1206CG821J500NT
designator C?  Capacitance: 820pF  (hidden comment: *)
Capacitor, Ceramic (MLCC), 820pF, ±5%, 50V, C0G, ±5%, SMD 1206; Manufacturer: FH(Guangdong Fenghua Advanced Tech); Manufacturer Part Number: 1206CG821J500NT
footprint CAP-1206 (1206 (3216M) Capacitor)
pins: 1, 2

## 1206F104Z500CT
designator C?  Capacitance: 100nF  (hidden comment: *)
Capacitor, Ceramic (MLCC), 100nF, 50V, Y5V, SMD 1206; Manufacturer: Walsin Tech Corp; Manufacturer Part Number: 1206F104Z500CT; Temperature Rating: -20%~+80%
footprint CAP-1206 (1206 (3216M) Capacitor)
pins: 1, 2

## 1206F105M500NT
designator C?  Capacitance: 1uF  (hidden comment: *)
Capacitor, Ceramic (MLCC), 1uF, ±20%, 50V, Y5V, ±20%, SMD 1206; Manufacturer: FH(Guangdong Fenghua Advanced Tech); Manufacturer Part Number: 1206F105M500NT
footprint CAP-1206 (1206 (3216M) Capacitor)
pins: 1, 2

## 1206F105Z160CT
designator C?  Capacitance: 1uF  (hidden comment: *)
Capacitor, Ceramic (MLCC), 1uF, 16V, Y5V, SMD 1206; Manufacturer: Walsin Tech Corp; Manufacturer Part Number: 1206F105Z160CT; Temperature Rating: -20%~+80%
footprint CAP-1206 (1206 (3216M) Capacitor)
pins: 1, 2

## 1206F105Z250
designator C?  Capacitance: 1uF  (hidden comment: *)
Capacitor, Ceramic (MLCC), 1uF, 25V, Y5V, SMD 1206; Manufacturer: Walsin Tech Corp; Manufacturer Part Number: 1206F105Z250; Temperature Rating: -20%~+80%
footprint CAP-1206 (1206 (3216M) Capacitor)
pins: 1, 2

## 1206F106M100NT
designator C?  Capacitance: 10uF  (hidden comment: *)
Capacitor, Ceramic (MLCC), 10uF, ±20%, 16V, Y5V, ±20%, SMD 1206; Manufacturer: FH(Guangdong Fenghua Advanced Tech); Manufacturer Part Number: 1206F106M100NT
footprint CAP-1206 (1206 (3216M) Capacitor)
pins: 1, 2

## 1206F106M160NT
designator C?  Capacitance: 10uF  (hidden comment: *)
Capacitor, Ceramic (MLCC), 10uF, ±20%, 16V, Y5V, ±20%, SMD 1206; Manufacturer: FH(Guangdong Fenghua Advanced Tech); Manufacturer Part Number: 1206F106M160NT
footprint CAP-1206 (1206 (3216M) Capacitor)
pins: 1, 2

## 1206F106M250CT
designator C?  Capacitance: 10uF  (hidden comment: *)
Capacitor, Ceramic (MLCC), 10uF, ±20%, 25V, Y5V, ±20%, SMD 1206; Manufacturer: Walsin Tech Corp; Manufacturer Part Number: 1206F106M250CT
footprint CAP-1206 (1206 (3216M) Capacitor)
pins: 1, 2

## 1206F106M250NT
designator C?  Capacitance: 10uF  (hidden comment: *)
Capacitor, Ceramic (MLCC), 10uF, ±20%, 25V, Y5V, ±20%, SMD 1206; Manufacturer: FH(Guangdong Fenghua Advanced Tech); Manufacturer Part Number: 1206F106M250NT
footprint CAP-1206 (1206 (3216M) Capacitor)
pins: 1, 2

## 1206F106M250NT_C3034761
designator C?  Capacitance: 10uF  (hidden comment: *)
Capacitor, Ceramic (MLCC), 10uF, ±20%, 25V, Y5V, ±20%, SMD 1206; Manufacturer: FH(Guangdong Fenghua Advanced Tech); Manufacturer Part Number: 1206F106M250NT
footprint CAP-1206 (1206 (3216M) Capacitor)
pins: 1, 2

## 1206F106M500NT
designator C?  Capacitance: 10uF  (hidden comment: *)
Capacitor, Ceramic (MLCC), 10uF, ±20%, 50V, Y5V, ±20%, SMD 1206; Manufacturer: FH(Guangdong Fenghua Advanced Tech); Manufacturer Part Number: 1206F106M500NT
footprint CAP-1206 (1206 (3216M) Capacitor)
pins: 1, 2

## 1206F106Z100CT
designator C?  Capacitance: 10uF  (hidden comment: *)
Capacitor, Ceramic (MLCC), 10uF, 10V, Y5V, SMD 1206; Manufacturer: Walsin Tech Corp; Manufacturer Part Number: 1206F106Z100CT; Temperature Rating: -20%~+80%
footprint CAP-1206 (1206 (3216M) Capacitor)
pins: 1, 2

## 1206F106Z160CT
designator C?  Capacitance: 10uF  (hidden comment: *)
Capacitor, Ceramic (MLCC), 10uF, 16V, Y5V, SMD 1206; Manufacturer: Walsin Tech Corp; Manufacturer Part Number: 1206F106Z160CT; Temperature Rating: -20%~+80%
footprint CAP-1206 (1206 (3216M) Capacitor)
pins: 1, 2

## 1206F106Z250CT
designator C?  Capacitance: 10uF  (hidden comment: *)
Capacitor, Ceramic (MLCC), 10uF, 25V, Y5V, SMD 1206; Manufacturer: Walsin Tech Corp; Manufacturer Part Number: 1206F106Z250CT; Temperature Rating: -20%~+80%
footprint CAP-1206 (1206 (3216M) Capacitor)
pins: 1, 2

## 1206F153M500NT
designator C?  Capacitance: 15nF  (hidden comment: *)
Capacitor, Ceramic (MLCC), 15nF, ±20%, 50V, Y5V, ±20%, SMD 1206; Manufacturer: FH(Guangdong Fenghua Advanced Tech); Manufacturer Part Number: 1206F153M500NT
footprint CAP-1206 (1206 (3216M) Capacitor)
pins: 1, 2

## 1206F154M500NT
designator C?  Capacitance: 150nF  (hidden comment: *)
Capacitor, Ceramic (MLCC), 150nF, ±20%, 50V, Y5V, ±20%, SMD 1206; Manufacturer: FH(Guangdong Fenghua Advanced Tech); Manufacturer Part Number: 1206F154M500NT
footprint CAP-1206 (1206 (3216M) Capacitor)
pins: 1, 2

## 1206F203M500NT
designator C?  Capacitance: 20nF  (hidden comment: *)
Capacitor, Ceramic (MLCC), 20nF, ±20%, 50V, Y5V, ±20%, SMD 1206; Manufacturer: FH(Guangdong Fenghua Advanced Tech); Manufacturer Part Number: 1206F203M500NT
footprint CAP-1206 (1206 (3216M) Capacitor)
pins: 1, 2

## 1206F223M500NT
designator C?  Capacitance: 22nF  (hidden comment: *)
Capacitor, Ceramic (MLCC), 22nF, ±20%, 50V, Y5V, ±20%, SMD 1206; Manufacturer: FH(Guangdong Fenghua Advanced Tech); Manufacturer Part Number: 1206F223M500NT
footprint CAP-1206 (1206 (3216M) Capacitor)
pins: 1, 2

## 1206F224M500NT
designator C?  Capacitance: 220nF  (hidden comment: *)
Capacitor, Ceramic (MLCC), 220nF, ±20%, 50V, Y5V, ±20%, SMD 1206; Manufacturer: FH(Guangdong Fenghua Advanced Tech); Manufacturer Part Number: 1206F224M500NT
footprint CAP-1206 (1206 (3216M) Capacitor)
pins: 1, 2

## 1206F225M250NT
designator C?  Capacitance: 2.2uF  (hidden comment: *)
Capacitor, Ceramic (MLCC), 2.2uF, ±20%, 25V, Y5V, ±20%, SMD 1206; Manufacturer: FH(Guangdong Fenghua Advanced Tech); Manufacturer Part Number: 1206F225M250NT
footprint CAP-1206 (1206 (3216M) Capacitor)
pins: 1, 2

## 1206F225Z160
designator C?  Capacitance: 2.2uF  (hidden comment: *)
Capacitor, Ceramic (MLCC), 2.2uF, 16V, Y5V, SMD 1206; Manufacturer: Walsin Tech Corp; Manufacturer Part Number: 1206F225Z160; Temperature Rating: -20%~+80%
footprint CAP-1206 (1206 (3216M) Capacitor)
pins: 1, 2

## 1206F225Z250CT
designator C?  Capacitance: 2.2uF  (hidden comment: *)
Capacitor, Ceramic (MLCC), 2.2uF, 25V, Y5V, SMD 1206; Manufacturer: Walsin Tech Corp; Manufacturer Part Number: 1206F225Z250CT; Temperature Rating: -20%~+80%
footprint CAP-1206 (1206 (3216M) Capacitor)
pins: 1, 2

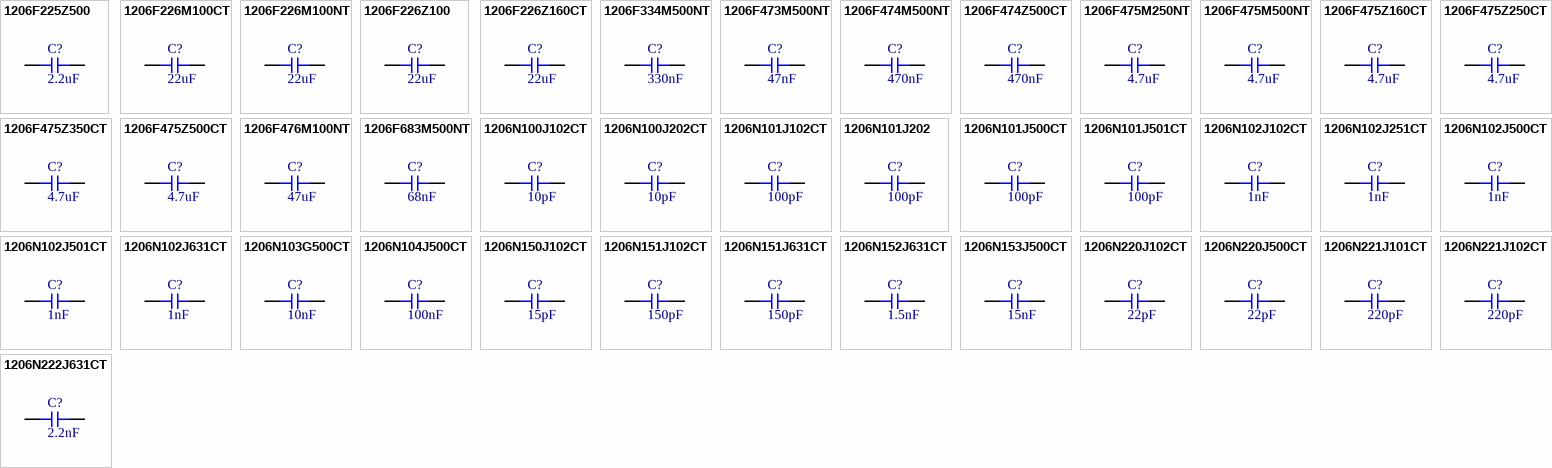
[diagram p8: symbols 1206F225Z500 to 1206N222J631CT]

## 1206F225Z500
designator C?  Capacitance: 2.2uF  (hidden comment: *)
Capacitor, Ceramic (MLCC), 2.2uF, 50V, Y5V, SMD 1206; Manufacturer: Walsin Tech Corp; Manufacturer Part Number: 1206F225Z500; Temperature Rating: -20%~+80%
footprint CAP-1206 (1206 (3216M) Capacitor)
pins: 1, 2

## 1206F226M100CT
designator C?  Capacitance: 22uF  (hidden comment: *)
Capacitor, Ceramic (MLCC), 22uF, ±20%, 10V, Y5V, ±20%, SMD 1206; Manufacturer: Walsin Tech Corp; Manufacturer Part Number: 1206F226M100CT
footprint CAP-1206 (1206 (3216M) Capacitor)
pins: 1, 2

## 1206F226M100NT
designator C?  Capacitance: 22uF  (hidden comment: *)
Capacitor, Ceramic (MLCC), 22uF, ±20%, 10V, Y5V, ±20%, SMD 1206; Manufacturer: FH(Guangdong Fenghua Advanced Tech); Manufacturer Part Number: 1206F226M100NT
footprint CAP-1206 (1206 (3216M) Capacitor)
pins: 1, 2

## 1206F226Z100
designator C?  Capacitance: 22uF  (hidden comment: *)
Capacitor, Ceramic (MLCC), 22uF, 10V, Y5V, SMD 1206; Manufacturer: Walsin Tech Corp; Manufacturer Part Number: 1206F226Z100; Temperature Rating: -20%~+80%
footprint CAP-1206 (1206 (3216M) Capacitor)
pins: 1, 2

## 1206F226Z160CT
designator C?  Capacitance: 22uF  (hidden comment: *)
Capacitor, Ceramic (MLCC), 22uF, 16V, Y5V, SMD 1206; Manufacturer: Walsin Tech Corp; Manufacturer Part Number: 1206F226Z160CT; Temperature Rating: -20%~+80%
footprint CAP-1206 (1206 (3216M) Capacitor)
pins: 1, 2

## 1206F334M500NT
designator C?  Capacitance: 330nF  (hidden comment: *)
Capacitor, Ceramic (MLCC), 330nF, ±20%, 50V, Y5V, ±20%, SMD 1206; Manufacturer: FH(Guangdong Fenghua Advanced Tech); Manufacturer Part Number: 1206F334M500NT
footprint CAP-1206 (1206 (3216M) Capacitor)
pins: 1, 2

## 1206F473M500NT
designator C?  Capacitance: 47nF  (hidden comment: *)
Capacitor, Ceramic (MLCC), 47nF, ±20%, 50V, Y5V, ±20%, SMD 1206; Manufacturer: FH(Guangdong Fenghua Advanced Tech); Manufacturer Part Number: 1206F473M500NT
footprint CAP-1206 (1206 (3216M) Capacitor)
pins: 1, 2

## 1206F474M500NT
designator C?  Capacitance: 470nF  (hidden comment: *)
Capacitor, Ceramic (MLCC), 470nF, ±20%, 50V, Y5V, ±20%, SMD 1206; Manufacturer: FH(Guangdong Fenghua Advanced Tech); Manufacturer Part Number: 1206F474M500NT
footprint CAP-1206 (1206 (3216M) Capacitor)
pins: 1, 2

## 1206F474Z500CT
designator C?  Capacitance: 470nF  (hidden comment: *)
Capacitor, Ceramic (MLCC), 470nF, 50V, Y5V, SMD 1206; Manufacturer: Walsin Tech Corp; Manufacturer Part Number: 1206F474Z500CT; Temperature Rating: -20%~+80%
footprint CAP-1206 (1206 (3216M) Capacitor)
pins: 1, 2

## 1206F475M250NT
designator C?  Capacitance: 4.7uF  (hidden comment: *)
Capacitor, Ceramic (MLCC), 4.7uF, ±20%, 25V, Y5V, ±20%, SMD 1206; Manufacturer: FH(Guangdong Fenghua Advanced Tech); Manufacturer Part Number: 1206F475M250NT
footprint CAP-1206 (1206 (3216M) Capacitor)
pins: 1, 2

## 1206F475M500NT
designator C?  Capacitance: 4.7uF  (hidden comment: *)
Capacitor, Ceramic (MLCC), 4.7uF, ±20%, 50V, Y5V, ±20%, SMD 1206; Manufacturer: FH(Guangdong Fenghua Advanced Tech); Manufacturer Part Number: 1206F475M500NT
footprint CAP-1206 (1206 (3216M) Capacitor)
pins: 1, 2

## 1206F475Z160CT
designator C?  Capacitance: 4.7uF  (hidden comment: *)
Capacitor, Ceramic (MLCC), 4.7uF, 16V, Y5V, SMD 1206; Manufacturer: Walsin Tech Corp; Manufacturer Part Number: 1206F475Z160CT; Temperature Rating: -20%~+80%
footprint CAP-1206 (1206 (3216M) Capacitor)
pins: 1, 2

## 1206F475Z250CT
designator C?  Capacitance: 4.7uF  (hidden comment: *)
Capacitor, Ceramic (MLCC), 4.7uF, 25V, Y5V, SMD 1206; Manufacturer: Walsin Tech Corp; Manufacturer Part Number: 1206F475Z250CT; Temperature Rating: -20%~+80%
footprint CAP-1206 (1206 (3216M) Capacitor)
pins: 1, 2

## 1206F475Z350CT
designator C?  Capacitance: 4.7uF  (hidden comment: *)
Capacitor, Ceramic (MLCC), 4.7uF, Y5V, SMD 1206; Manufacturer: Walsin Tech Corp; Manufacturer Part Number: 1206F475Z350CT; Temperature Rating: -20%~+80%
footprint CAP-1206 (1206 (3216M) Capacitor)
pins: 1, 2

## 1206F475Z500CT
designator C?  Capacitance: 4.7uF  (hidden comment: *)
Capacitor, Ceramic (MLCC), 4.7uF, 50V, Y5V, SMD 1206; Manufacturer: Walsin Tech Corp; Manufacturer Part Number: 1206F475Z500CT; Temperature Rating: -20%~+80%
footprint CAP-1206 (1206 (3216M) Capacitor)
pins: 1, 2

## 1206F476M100NT
designator C?  Capacitance: 47uF  (hidden comment: *)
Capacitor, Ceramic (MLCC), 47uF, ±20%, 10V, Y5V, ±20%, SMD 1206; Manufacturer: FH(Guangdong Fenghua Advanced Tech); Manufacturer Part Number: 1206F476M100NT
footprint CAP-1206 (1206 (3216M) Capacitor)
pins: 1, 2

## 1206F683M500NT
designator C?  Capacitance: 68nF  (hidden comment: *)
Capacitor, Ceramic (MLCC), 68nF, ±20%, 50V, Y5V, ±20%, SMD 1206; Manufacturer: FH(Guangdong Fenghua Advanced Tech); Manufacturer Part Number: 1206F683M500NT
footprint CAP-1206 (1206 (3216M) Capacitor)
pins: 1, 2

## 1206N100J102CT
designator C?  Capacitance: 10pF  (hidden comment: *)
Capacitor, Ceramic (MLCC), 10pF, ±5%, 1kV, NP0, ±5%, SMD 1206; Manufacturer: Walsin Tech Corp; Manufacturer Part Number: 1206N100J102CT
footprint CAP-1206 (1206 (3216M) Capacitor)
pins: 1, 2

## 1206N100J202CT
designator C?  Capacitance: 10pF  (hidden comment: *)
Capacitor, Ceramic (MLCC), 10pF, ±5%, 2kV, NP0, ±5%, SMD 1206; Manufacturer: Walsin Tech Corp; Manufacturer Part Number: 1206N100J202CT
footprint CAP-1206 (1206 (3216M) Capacitor)
pins: 1, 2

## 1206N101J102CT
designator C?  Capacitance: 100pF  (hidden comment: *)
Capacitor, Ceramic (MLCC), 100pF, ±5%, 1kV, NP0, ±5%, SMD 1206; Manufacturer: Walsin Tech Corp; Manufacturer Part Number: 1206N101J102CT
footprint CAP-1206 (1206 (3216M) Capacitor)
pins: 1, 2

## 1206N101J202
designator C?  Capacitance: 100pF  (hidden comment: *)
Capacitor, Ceramic (MLCC), 100pF, ±5%, 2kV, NP0, ±5%, SMD 1206; Manufacturer: Walsin Tech Corp; Manufacturer Part Number: 1206N101J202
footprint CAP-1206 (1206 (3216M) Capacitor)
pins: 1, 2

## 1206N101J500CT
designator C?  Capacitance: 100pF  (hidden comment: *)
Capacitor, Ceramic (MLCC), 100pF, ±5%, 50V, NP0, ±5%, SMD 1206; Manufacturer: Walsin Tech Corp; Manufacturer Part Number: 1206N101J500CT
footprint CAP-1206 (1206 (3216M) Capacitor)
pins: 1, 2

## 1206N101J501CT
designator C?  Capacitance: 100pF  (hidden comment: *)
Capacitor, Ceramic (MLCC), 100pF, ±5%, 500V, NP0, ±5%, SMD 1206; Manufacturer: Walsin Tech Corp; Manufacturer Part Number: 1206N101J501CT
footprint CAP-1206 (1206 (3216M) Capacitor)
pins: 1, 2

## 1206N102J102CT
designator C?  Capacitance: 1nF  (hidden comment: *)
Capacitor, Ceramic (MLCC), 1nF, ±5%, 1kV, NP0, ±5%, SMD 1206; Manufacturer: Walsin Tech Corp; Manufacturer Part Number: 1206N102J102CT
footprint CAP-1206 (1206 (3216M) Capacitor)
pins: 1, 2

## 1206N102J251CT
designator C?  Capacitance: 1nF  (hidden comment: *)
Capacitor, Ceramic (MLCC), 1nF, ±5%, 250V, NP0, ±5%, SMD 1206; Manufacturer: Walsin Tech Corp; Manufacturer Part Number: 1206N102J251CT
footprint CAP-1206 (1206 (3216M) Capacitor)
pins: 1, 2

## 1206N102J500CT
designator C?  Capacitance: 1nF  (hidden comment: *)
Capacitor, Ceramic (MLCC), 1nF, ±5%, 50V, NP0, ±5%, SMD 1206; Manufacturer: Walsin Tech Corp; Manufacturer Part Number: 1206N102J500CT
footprint CAP-1206 (1206 (3216M) Capacitor)
pins: 1, 2

## 1206N102J501CT
designator C?  Capacitance: 1nF  (hidden comment: *)
Capacitor, Ceramic (MLCC), 1nF, ±5%, 500V, NP0, ±5%, SMD 1206; Manufacturer: Walsin Tech Corp; Manufacturer Part Number: 1206N102J501CT
footprint CAP-1206 (1206 (3216M) Capacitor)
pins: 1, 2

## 1206N102J631CT
designator C?  Capacitance: 1nF  (hidden comment: *)
Capacitor, Ceramic (MLCC), 1nF, ±5%, 630V, NP0, ±5%, SMD 1206; Manufacturer: Walsin Tech Corp; Manufacturer Part Number: 1206N102J631CT
footprint CAP-1206 (1206 (3216M) Capacitor)
pins: 1, 2

## 1206N103G500CT
designator C?  Capacitance: 10nF  (hidden comment: *)
Capacitor, Ceramic (MLCC), 10nF, ±2%, 50V, NP0, ±2%, SMD 1206; Manufacturer: Walsin Tech Corp; Manufacturer Part Number: 1206N103G500CT
footprint CAP-1206 (1206 (3216M) Capacitor)
pins: 1, 2

## 1206N104J500CT
designator C?  Capacitance: 100nF  (hidden comment: *)
Capacitor, Ceramic (MLCC), 100nF, ±5%, 50V, NP0, ±5%, SMD 1206; Manufacturer: Walsin Tech Corp; Manufacturer Part Number: 1206N104J500CT
footprint CAP-1206 (1206 (3216M) Capacitor)
pins: 1, 2

## 1206N150J102CT
designator C?  Capacitance: 15pF  (hidden comment: *)
Capacitor, Ceramic (MLCC), 15pF, ±5%, 1kV, NP0, ±5%, SMD 1206; Manufacturer: Walsin Tech Corp; Manufacturer Part Number: 1206N150J102CT
footprint CAP-1206 (1206 (3216M) Capacitor)
pins: 1, 2

## 1206N151J102CT
designator C?  Capacitance: 150pF  (hidden comment: *)
Capacitor, Ceramic (MLCC), 150pF, ±5%, 1kV, NP0, ±5%, SMD 1206; Manufacturer: Walsin Tech Corp; Manufacturer Part Number: 1206N151J102CT
footprint CAP-1206 (1206 (3216M) Capacitor)
pins: 1, 2

## 1206N151J631CT
designator C?  Capacitance: 150pF  (hidden comment: *)
Capacitor, Ceramic (MLCC), 150pF, ±5%, 630V, NP0, ±5%, SMD 1206; Manufacturer: Walsin Tech Corp; Manufacturer Part Number: 1206N151J631CT
footprint CAP-1206 (1206 (3216M) Capacitor)
pins: 1, 2

## 1206N152J631CT
designator C?  Capacitance: 1.5nF  (hidden comment: *)
Capacitor, Ceramic (MLCC), 1.5nF, ±5%, 630V, NP0, ±5%, SMD 1206; Manufacturer: Walsin Tech Corp; Manufacturer Part Number: 1206N152J631CT
footprint CAP-1206 (1206 (3216M) Capacitor)
pins: 1, 2

## 1206N153J500CT
designator C?  Capacitance: 15nF  (hidden comment: *)
Capacitor, Ceramic (MLCC), 15nF, ±5%, 50V, NP0, ±5%, SMD 1206; Manufacturer: Walsin Tech Corp; Manufacturer Part Number: 1206N153J500CT
footprint CAP-1206 (1206 (3216M) Capacitor)
pins: 1, 2

## 1206N220J102CT
designator C?  Capacitance: 22pF  (hidden comment: *)
Capacitor, Ceramic (MLCC), 22pF, ±5%, 1kV, NP0, ±5%, SMD 1206; Manufacturer: Walsin Tech Corp; Manufacturer Part Number: 1206N220J102CT
footprint CAP-1206 (1206 (3216M) Capacitor)
pins: 1, 2

## 1206N220J500CT
designator C?  Capacitance: 22pF  (hidden comment: *)
Capacitor, Ceramic (MLCC), 22pF, ±5%, 50V, NP0, ±5%, SMD 1206; Manufacturer: Walsin Tech Corp; Manufacturer Part Number: 1206N220J500CT
footprint CAP-1206 (1206 (3216M) Capacitor)
pins: 1, 2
